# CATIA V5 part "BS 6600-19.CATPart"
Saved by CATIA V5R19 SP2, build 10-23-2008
Part number: BS 6600-19
Bounding box of the stored display mesh (mm): x -59.975 to 59.975, y -59.975 to 59.975, z 0 to 113
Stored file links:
  C:\Users\Bora\Desktop\3D Katı model\BS serisi\BS 6600\BS 6600-19.CATPart
  C:\Program Files\Dassault Systemes\B19\intel_a\reffiles\standard\MetricThickPitch.txt
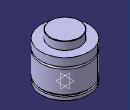
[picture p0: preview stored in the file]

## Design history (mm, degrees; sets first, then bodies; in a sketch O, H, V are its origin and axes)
Body1 (main body)
  Sketch1 on yz-plane, origin (0, 0, 0), H (0, 1, 0), V (0, 0, 1)
    point P1 (60, 73)
    point P2 (60, 68)
    point P3 (60, 73)
    point P7 (37.5, 112)
    point P9 (37.5, 112)
    point P14 (60, 68)
    arc A1 centre (60, 70.5) radius 2.5 from (60, 73) to (60, 68) ccw
    line L1 (60, 73) -> (60, 93)
    line L2 (60, 0) -> (60, 8)
    arc A2 centre (36.5, 112) radius 1 from (37.5, 112) to (36.5, 113) ccw
    line L3 (37.5, 112) -> (37.5, 93)
    line L4 (56, 13) -> (56, 8)
    line L5 (60, 13) -> (60, 68)
    line L6 (36.5, 113) -> (0, 113)
    point P15 (0, 113)
    line L7 (37.5, 93) -> (60, 93)
    line L8 (0, 0) -> (60, 0)
    line L9 (56, 13) -> (60, 13)
    line L10 (56, 8) -> (60, 8)
    coincidence: P15 V, P1 P3, P2 P14, P7 P9
    tangency: L6 A2
    horizontal: L7 H, L8 H, L9 H, L10 H
  Shaft1: profile Sketch1, axis Sketch1.V, angle 360
  Sketch2 on face of Shaft1 from Sketch1.L8, origin (0, 0, 0), H (1, 0, 0), V (0, -1, 0)
    point P1 (40, 0)
    distance P1 V = 40
  Hole1: placed by Sketch2, at (40, 0, 0) direction (0, 0, 1), diameter 8.376, depth 8, threaded "M10", thread diameter 10, thread depth 8, pitch 1.5
  CircPattern1: of Hole1, instances 4, angular step 90, axis from xy-plane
